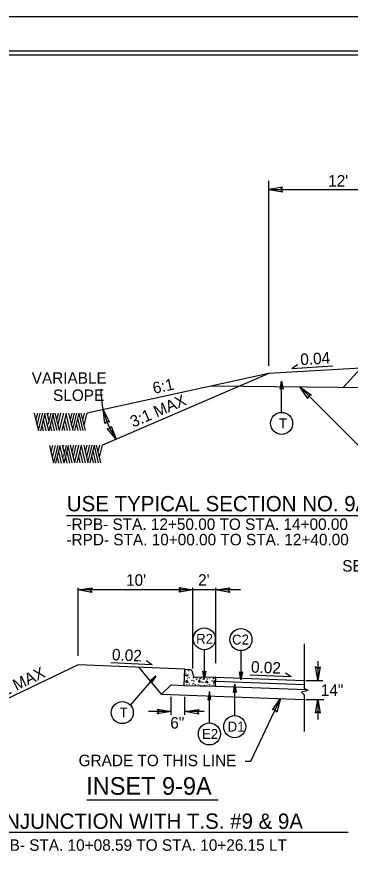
# Model space of a CAD drawing. Extents: x 573748 to 574632, y -54663 to -53209.
# Drawn here: x 574108.2 to 574151.8, y -54257.8 to -54148.7 of the extents above; entities that cross this region are included whole.
import ezdxf

# ---------------------------------------------------------------- set-up
doc = ezdxf.new("R2010")
doc.units = 0
for name, color, linetype in [('Prop Dimension', 7, 'Continuous'), ('Prop Dimension Text', 7, 'Continuous'), ('Prop Terminator CELL', 7, 'Continuous'), ('Sheet Cutting Line CELL', 7, 'Continuous'), ('Sheet Plot Border Inside CELL', 7, 'Continuous'), ('Sheet Plot Border Outside CELL', 7, 'Continuous'), ('Sheet Typical CELL', 7, 'Continuous'), ('Typical Arrow Superelevation CELL', 7, 'Continuous'), ('Typical Curb CELL', 7, 'Continuous'), ('Typical Hinge Slope Arterial CELL', 7, 'Continuous'), ('Typical ID Circle CELL', 7, 'Continuous'), ('Typical Pavement Slope CELL', 7, 'Continuous'), ('Typical Slope Point Local CELL', 7, 'Continuous'), ('Typical Terminator CELL', 7, 'Continuous'), ('Typical Text General CELL', 7, 'Continuous'), ('Typical Text ID Circle CELL', 7, 'Continuous'), ('Typical Text Label CELL', 7, 'Continuous')]:
    doc.layers.add(name, color=color, linetype=linetype)

msp = doc.modelspace()

# ---------------------------------------------------------------- linework, layer by layer
at = {"layer": 'Prop Dimension'}
for p, q in [((574141.18, -54194.26), (574141.18, -54170.11)), ((574141.18, -54171.24), (574159.18, -54171.24)), ((574116.26, -54232.12), (574116.26, -54223.22)), ((574131.26, -54233.77), (574131.26, -54223.22)), ((574134.26, -54233.08), (574134.26, -54223.22)), ((574131.26, -54223.52), (574116.26, -54223.52)), ((574137.46, -54223.52), (574131.26, -54223.52)), ((574145.79, -54230.54), (574145.79, -54236.36)), ((574147.58, -54232.83), (574147.58, -54235.34)), ((574145.79, -54236.36), (574146.3, -54236.66)), ((574146.03, -54235.34), (574148.25, -54235.34)), ((574128.4, -54239.83), (574128.4, -54237.47)), ((574130.21, -54239.83), (574130.21, -54237.48)), ((574146.3, -54236.66), (574145.43, -54236.86)), ((574145.43, -54236.86), (574145.79, -54237.21)), ((574145.79, -54237.21), (574145.79, -54242)), ((574146.01, -54237.81), (574148.36, -54237.81)), ((574147.58, -54237.81), (574147.58, -54240.43)), ((574128.4, -54239.41), (574125.46, -54239.41)), ((574132.73, -54239.41), (574130.21, -54239.41))]:
    msp.add_line(p, q, dxfattribs=at)
for points in [[(574157.4, -54208.24), (574156.45, -54208.24), (574145.22, -54197.01)], [(574138.08, -54245.89), (574138.83, -54245.89), (574142.69, -54237.69)]]:
    msp.add_lwpolyline(points, dxfattribs=at)
msp.add_arc((574130.35, -54197.47), 11.12, 179.1001, 214.9438, dxfattribs=at)
at = {"layer": 'Prop Terminator CELL'}
for points in [[(574142.97, -54170.91), (574141.18, -54171.24), (574142.99, -54171.54), (574142.76, -54171.22)], [(574146.28, -54198.5), (574145.22, -54197.01), (574146.73, -54198.06), (574146.34, -54198.13)], [(574119.75, -54201.78), (574119.51, -54199.97), (574120.36, -54201.6), (574119.98, -54201.48)], [(574120.57, -54202.13), (574121.23, -54203.84), (574120.03, -54202.45), (574120.42, -54202.48)], [(574118.06, -54223.85), (574116.26, -54223.52), (574118.07, -54223.22), (574117.84, -54223.54)], [(574129.46, -54223.18), (574131.26, -54223.52), (574129.44, -54223.81), (574129.68, -54223.5)], [(574136.06, -54223.85), (574134.26, -54223.52), (574136.07, -54223.22), (574135.84, -54223.54)], [(574147.89, -54233.54), (574147.58, -54235.34), (574147.26, -54233.53), (574147.58, -54233.76)], [(574141.64, -54239.19), (574142.69, -54237.69), (574142.21, -54239.47), (574142.02, -54239.12)], [(574147.27, -54239.61), (574147.58, -54237.81), (574147.9, -54239.62), (574147.58, -54239.39)], [(574126.6, -54239.08), (574128.4, -54239.41), (574126.58, -54239.71), (574126.82, -54239.39)], [(574132.01, -54239.74), (574130.21, -54239.41), (574132.03, -54239.11), (574131.79, -54239.43)]]:
    msp.add_lwpolyline(points, close=True, dxfattribs=at)
at = {"layer": 'Sheet Cutting Line CELL'}
msp.add_line((574280.97, -54148.66), (573944.17, -54148.66), dxfattribs=at)
at = {"layer": 'Sheet Plot Border Inside CELL'}
msp.add_lwpolyline([(574280.07, -54153.15), (573946.77, -54153.15), (573946.77, -54364.17), (574280.07, -54364.17)], close=True, dxfattribs=at)
at = {"layer": 'Sheet Plot Border Outside CELL'}
msp.add_lwpolyline([(574280.97, -54148.66), (573944.17, -54148.66), (573944.17, -54368.66), (574280.97, -54368.66)], close=True, dxfattribs=at)
at = {"layer": 'Sheet Typical CELL'}
msp.add_lwpolyline([(574277.57, -54153.66), (573977.57, -54153.66), (573977.57, -54363.66), (574277.57, -54363.66)], close=True, dxfattribs=at)
at = {"layer": 'Typical Arrow Superelevation CELL'}
for p, q in [((574144.17, -54194.58), (574144.93, -54194.08)), ((574144.17, -54194.58), (574149.55, -54194.25)), ((574125.92, -54233.28), (574120.54, -54233.03)), ((574125.92, -54233.28), (574125.15, -54232.78)), ((574144.1, -54234.86), (574138.71, -54234.64)), ((574144.1, -54234.86), (574143.33, -54234.37))]:
    msp.add_line(p, q, dxfattribs=at)
at = {"layer": 'Typical Curb CELL'}
for p, q in [((574130.1, -54235.98), (574130.21, -54233.88)), ((574130.21, -54233.88), (574130.75, -54233.9)), ((574130.26, -54234.68), (574130.59, -54234.59)), ((574130.55, -54234.78), (574130.26, -54234.68)), ((574130.59, -54234.59), (574130.55, -54234.78)), ((574131.24, -54234.43), (574131.24, -54234.41)), ((574134.26, -54234.91), (574131.75, -54234.95)), ((574132.07, -54235.27), (574131.99, -54235.51)), ((574132.24, -54235.53), (574132.07, -54235.27)), ((574134.2, -54236.08), (574134.26, -54234.91)), ((574130.1, -54235.98), (574134.2, -54236.08)), ((574130.51, -54235.35), (574130.29, -54235.5)), ((574130.29, -54235.5), (574130.64, -54235.59)), ((574130.64, -54235.59), (574130.51, -54235.35)), ((574131.99, -54235.51), (574132.24, -54235.53)), ((574133.13, -54235.42), (574132.91, -54235.57)), ((574132.91, -54235.57), (574133.25, -54235.66)), ((574133.25, -54235.66), (574133.13, -54235.42)), ((574134.02, -54235.36), (574133.94, -54235.59)), ((574133.94, -54235.59), (574134.19, -54235.61)), ((574134.19, -54235.61), (574134.02, -54235.36))]:
    msp.add_line(p, q, dxfattribs=at)
for centre in [(574130.23, -54234.11), (574130.69, -54234.05), (574130.33, -54234.5), (574130.52, -54235.08), (574130.77, -54234.98), (574131.13, -54235.33), (574131.31, -54234.93), (574131.34, -54235.04), (574131.71, -54235.23), (574131.77, -54235.01), (574132.18, -54235.11), (574132.39, -54235), (574132.61, -54235.2), (574132.73, -54235.13), (574132.76, -54235.34), (574133.13, -54235.14), (574133.39, -54235.04), (574133.93, -54235), (574133.96, -54235.1), (574134.2, -54235.15), (574130.46, -54235.89), (574130.82, -54235.81), (574131.19, -54235.95), (574131.31, -54235.72), (574131.39, -54235.4), (574131.55, -54235.9), (574131.98, -54235.87), (574132.31, -54236.02), (574132.43, -54235.53), (574132.63, -54235.63), (574132.75, -54235.98), (574133.08, -54235.95), (574133.44, -54235.88), (574133.75, -54235.4), (574133.81, -54236.02), (574133.93, -54235.78), (574134.17, -54235.97)]:
    msp.add_circle(centre, 0.0168, dxfattribs=at)
for centre, start, end in [((574130.74, -54234.4), 358.5664, 88.5664), ((574131.74, -54234.45), 178.5664, 270.9508)]:
    msp.add_arc(centre, 0.502, start, end, dxfattribs=at)
at = {"layer": 'Typical Hinge Slope Arterial CELL'}
for p, q in [((574141.18, -54195.26), (574117.42, -54200.42)), ((574141.18, -54195.26), (574119.42, -54204.62)), ((574116.26, -54233.3), (574100.92, -54240.64))]:
    msp.add_line(p, q, dxfattribs=at)
at = {"layer": 'Typical ID Circle CELL'}
for p, q in [((574142.84, -54200.33), (574142.84, -54196.24)), ((574132.74, -54231.34), (574132.74, -54235.17)), ((574137.53, -54231.44), (574137.53, -54235.27)), ((574123.08, -54238.56), (574126.39, -54234.74)), ((574136.72, -54239.93), (574136.72, -54235.84)), ((574133.41, -54240.87), (574133.41, -54236.79))]:
    msp.add_line(p, q, dxfattribs=at)
for centre in [(574142.84, -54201.77), (574132.74, -54229.9), (574137.53, -54230), (574122.02, -54239.53), (574136.72, -54241.37), (574133.41, -54242.31)]:
    msp.add_circle(centre, 1.44, dxfattribs=at)
at = {"layer": 'Typical Pavement Slope CELL'}
for p, q in [((574153.18, -54194.56), (574141.18, -54195.26)), ((574150.88, -54197.07), (574153.18, -54194.56)), ((574159.18, -54197.15), (574133.66, -54196.89)), ((574130.21, -54233.88), (574116.26, -54233.3)), ((574127.16, -54237.11), (574124.24, -54233.63)), ((574134.26, -54234.91), (574145.79, -54235.34)), ((574127.16, -54237.11), (574128.4, -54235.91)), ((574128.4, -54235.91), (574130.1, -54235.98)), ((574134.2, -54236.08), (574146.06, -54236.52)), ((574134.26, -54235.43), (574145.79, -54235.87)), ((574127.16, -54237.11), (574145.79, -54237.81))]:
    msp.add_line(p, q, dxfattribs=at)
at = {"layer": 'Typical Slope Point Local CELL'}
for p, q in [((574111.1, -54202.74), (574110.53, -54200.44)), ((574110.74, -54201.32), (574110.96, -54200.45)), ((574110.91, -54202.01), (574111.3, -54200.45)), ((574111.08, -54202.67), (574111.63, -54200.45)), ((574111.36, -54202.74), (574111.93, -54200.45)), ((574112.09, -54202.74), (574111.73, -54201.26)), ((574112.44, -54202.74), (574111.9, -54200.57)), ((574112.45, -54201.42), (574112.21, -54200.45)), ((574112.32, -54200.53), (574112.35, -54200.42)), ((574112.36, -54201.88), (574112.72, -54200.45)), ((574112.36, -54200.56), (574112.39, -54200.45)), ((574112.43, -54201.29), (574112.45, -54201.2)), ((574112.45, -54202.74), (574113.02, -54200.45)), ((574113.18, -54202.74), (574112.82, -54201.26)), ((574113.49, -54202.7), (574112.95, -54200.53)), ((574113.82, -54202.7), (574113.26, -54200.42)), ((574113.47, -54201.26), (574113.68, -54200.42)), ((574113.63, -54201.93), (574114, -54200.42)), ((574113.81, -54202.64), (574114.36, -54200.42)), ((574114.14, -54202.7), (574114.71, -54200.42)), ((574114.87, -54202.7), (574114.51, -54201.22)), ((574115.22, -54202.7), (574114.68, -54200.53)), ((574115.59, -54202.7), (574115.02, -54200.42)), ((574115.24, -54201.29), (574115.45, -54200.42)), ((574115.4, -54201.95), (574115.78, -54200.42)), ((574115.55, -54202.56), (574115.82, -54201.49)), ((574115.82, -54201.49), (574116.08, -54200.42)), ((574115.82, -54202.7), (574116.39, -54200.42)), ((574116.58, -54202.7), (574116.21, -54201.15)), ((574116.92, -54202.7), (574116.37, -54200.49)), ((574117.22, -54202.7), (574116.66, -54200.41)), ((574116.87, -54201.29), (574117.08, -54200.42)), ((574117.04, -54201.97), (574117.42, -54200.42)), ((574111.73, -54202.74), (574111.55, -54201.97)), ((574112.82, -54202.74), (574112.64, -54201.97)), ((574114.53, -54202.7), (574114.34, -54201.91)), ((574116.26, -54202.7), (574116.04, -54201.8)), ((574113.09, -54206.94), (574112.53, -54204.64)), ((574112.74, -54205.52), (574112.95, -54204.65)), ((574112.91, -54206.2), (574113.3, -54204.65)), ((574113.08, -54206.86), (574113.62, -54204.65)), ((574113.35, -54206.94), (574113.92, -54204.65)), ((574114.43, -54206.94), (574113.89, -54204.77)), ((574114.45, -54205.61), (574114.21, -54204.65)), ((574114.32, -54204.72), (574114.34, -54204.62)), ((574114.36, -54206.08), (574114.71, -54204.65)), ((574114.36, -54204.76), (574114.38, -54204.65)), ((574114.44, -54206.94), (574115.01, -54204.65)), ((574115.48, -54206.9), (574114.95, -54204.73)), ((574115.82, -54206.9), (574115.26, -54204.62)), ((574115.47, -54205.46), (574115.67, -54204.62)), ((574115.63, -54206.12), (574116, -54204.62)), ((574115.8, -54206.83), (574116.35, -54204.62)), ((574116.14, -54206.9), (574116.71, -54204.62)), ((574117.22, -54206.9), (574116.68, -54204.72)), ((574117.58, -54206.9), (574117.02, -54204.62)), ((574117.23, -54205.49), (574117.45, -54204.62)), ((574117.4, -54206.15), (574117.78, -54204.62)), ((574117.82, -54205.68), (574118.08, -54204.62)), ((574117.82, -54206.9), (574118.38, -54204.62)), ((574118.91, -54206.9), (574118.37, -54204.68)), ((574119.22, -54206.9), (574118.65, -54204.6)), ((574118.86, -54205.48), (574119.08, -54204.62)), ((574119.04, -54206.17), (574119.42, -54204.62)), ((574114.08, -54206.94), (574113.72, -54205.45)), ((574114.42, -54205.49), (574114.45, -54205.4)), ((574115.17, -54206.94), (574114.81, -54205.45)), ((574116.87, -54206.9), (574116.51, -54205.41)), ((574117.55, -54206.76), (574117.82, -54205.68)), ((574118.58, -54206.9), (574118.2, -54205.34)), ((574113.73, -54206.94), (574113.54, -54206.17)), ((574114.82, -54206.94), (574114.64, -54206.17)), ((574116.52, -54206.9), (574116.34, -54206.11)), ((574118.26, -54206.9), (574118.04, -54206))]:
    msp.add_line(p, q, dxfattribs=at)
at = {"layer": 'Typical Terminator CELL'}
for points in [[(574142.66, -54197.3), (574142.84, -54196.24), (574143.03, -54197.3), (574142.84, -54197.17)], [(574132.92, -54234.11), (574132.74, -54235.17), (574132.56, -54234.11), (574132.74, -54234.24)], [(574137.71, -54234.21), (574137.53, -54235.27), (574137.34, -54234.2), (574137.53, -54234.34)], [(574125.56, -54235.42), (574126.39, -54234.74), (574125.84, -54235.66), (574125.78, -54235.44)], [(574136.54, -54236.9), (574136.72, -54235.84), (574136.91, -54236.9), (574136.72, -54236.77)], [(574133.59, -54237.84), (574133.41, -54236.79), (574133.22, -54237.85), (574133.41, -54237.71)]]:
    msp.add_lwpolyline(points, close=True, dxfattribs=at)
at = {"layer": 'Typical Text General CELL'}
for p, q in [((574114.72, -54213.8), (574154.71, -54213.8)), ((574151.54, -54255.21), (574092.76, -54255.21))]:
    msp.add_line(p, q, dxfattribs=at)
at = {"layer": 'Typical Text Label CELL'}
msp.add_line((574134.56, -54250.98), (574117.37, -54250.98), dxfattribs=at)

# ---------------------------------------------------------------- texts
at = {"layer": 'Prop Dimension'}
msp.add_text('GRADE TO THIS LINE', height=1.5, dxfattribs=at).set_placement((574116.31, -54246.53))
at = {"layer": 'Prop Dimension Text'}
for s, height, p in [("12'", 1.5, (574148.93, -54170.84)), ("10'", 1.5, (574122.51, -54222.97)), ("2'", 1.5, (574131.93, -54222.96)), ('14"', 1.5, (574147.96, -54237.35)), ('6"', 1.5, (574128.29, -54241.62)), ('INSET 9-9A', 2.3, (574117.3, -54250.26))]:
    msp.add_text(s, height=height, dxfattribs=at).set_placement(p)
for s, rotation, p in [('0.04', 3.5612, (574145.33, -54194.17)), ('6:1', 12.2721, (574126.16, -54197.92)), ('3:1 MAX', 23.1063, (574123.44, -54202.32)), ('0.02', 357.3706, (574120.64, -54232.69)), ('0.02', 357.6243, (574138.82, -54234.3)), ('3:1 MAX', 25.5792, (574105.14, -54238.15))]:
    msp.add_text(s, height=1.5, rotation=rotation, dxfattribs=at).set_placement(p)
at = {"layer": 'Typical Text General CELL'}
for s, height, p in [('VARIABLE', 1.5, (574110.18, -54196.59)), ('SLOPE', 1.5, (574112.97, -54198.84)), ('USE TYPICAL SECTION NO. 9A', 2, (574114.77, -54213.25)), ('-RPB- STA. 12+50.00 TO STA. 14+00.00', 1.5, (574114.72, -54215.68)), ('-RPD- STA. 10+00.00 TO STA. 12+40.00', 1.5, (574114.72, -54217.69)), ('SEE SHEET 2A-6 FOR AGGREGATE SUBGRADE DETAIL', 1.5, (574150.77, -54221.12)), ('USE IN CONJUNCTION WITH T.S. #9 & 9A', 2, (574093.03, -54254.71)), ('-RPB- STA. 10+08.59 TO STA. 10+26.15 LT', 1.5, (574103.84, -54257.58))]:
    msp.add_text(s, height=height, dxfattribs=at).set_placement(p)
at = {"layer": 'Typical Text ID Circle CELL'}
for s, height, p in [('T', 1.29, (574142.49, -54202.41)), ('R2', 1.291, (574131.67, -54230.54)), ('C2', 1.291, (574136.37, -54230.64)), ('T', 1.29, (574121.67, -54240.17)), ('D1', 1.291, (574135.79, -54242.01)), ('E2', 1.291, (574132.43, -54242.96))]:
    msp.add_text(s, height=height, dxfattribs=at).set_placement(p)

doc.saveas('drawing.dxf')
